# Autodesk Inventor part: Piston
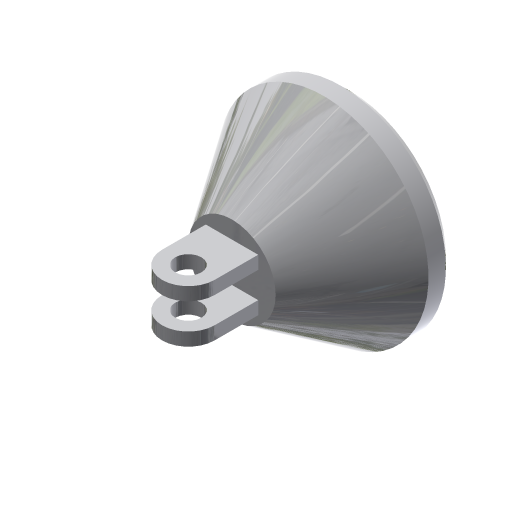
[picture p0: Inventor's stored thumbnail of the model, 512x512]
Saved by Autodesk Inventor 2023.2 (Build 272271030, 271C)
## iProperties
Created: 2013-02
Part Number: Piston
Material: PVC-Piping
Document SubType Name: Modeling
Designer: Formateur
Density: 1 g/cm^3
Appearance: Smooth - White
Author: Formateur
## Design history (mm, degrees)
sketch "Sketch1"
  geometry: L1 (0, 0)-(0, 27); L2 (0, 27)-(-24, 27); L3 (-24, 27)-(-24, 21); L4 (-24, 21)-(-10, 0); L5 (-10, 0)-(0, 0); L6 (-6, 0)-(-6, -10); L7 (6, -10)-(6, 0); L8 (6, 0)-(-6, 0); A1 r 6 centre (0, -10) between (-6, -10) and (6, -10)
  constraints: 16 end point, 3 parallel, 2 perpendicular, 2 point on circle, 2 tangent, 1 centre point, 1 collinear, 1 midpoint, 1 point on line, 1 vertical
  dimensions: "d0" = 27 distance of L1.start L1.end; "d1" = 24 distance of L1.end L2.end; "d2" = 6 distance of L2.end L3.end; "d3" = 10 distance of L4.end L1.start; "d4" = 6 radius of A1; "d5" = 10 distance of L7.start L7.end
revolve "Revolution1" stored, may be unused: angle "d6" = 90 deg
extrude "Extrusion1" join sketch "Sketch1" stored distance "d7" = 12; taper "d8" = 0 deg
extrude "Extrusion2" cut sketch "Sketch1" stored distance "d9" = 6; taper "d10" = 0 deg
hole "Hole1" diameter "d13" = 6; stored, may be unused: countersink angle "d17" = 90 deg, drill point angle "d19" = 118 deg; dims "d11" = 10, "d12" = 10, "d14" = 6, "d15" = 4, "d16" = 2, "d18" = 8
chamfer "Chamfer1" distance "d20" = 2; stored, may be unused: second distance "d21" = 2, angle "d22" = 45 deg
body "Solid1"
other parameters: "DIA" = 5 [user parameter]
